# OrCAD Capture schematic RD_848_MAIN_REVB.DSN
size Custom; title: DER-804; rev: RevA
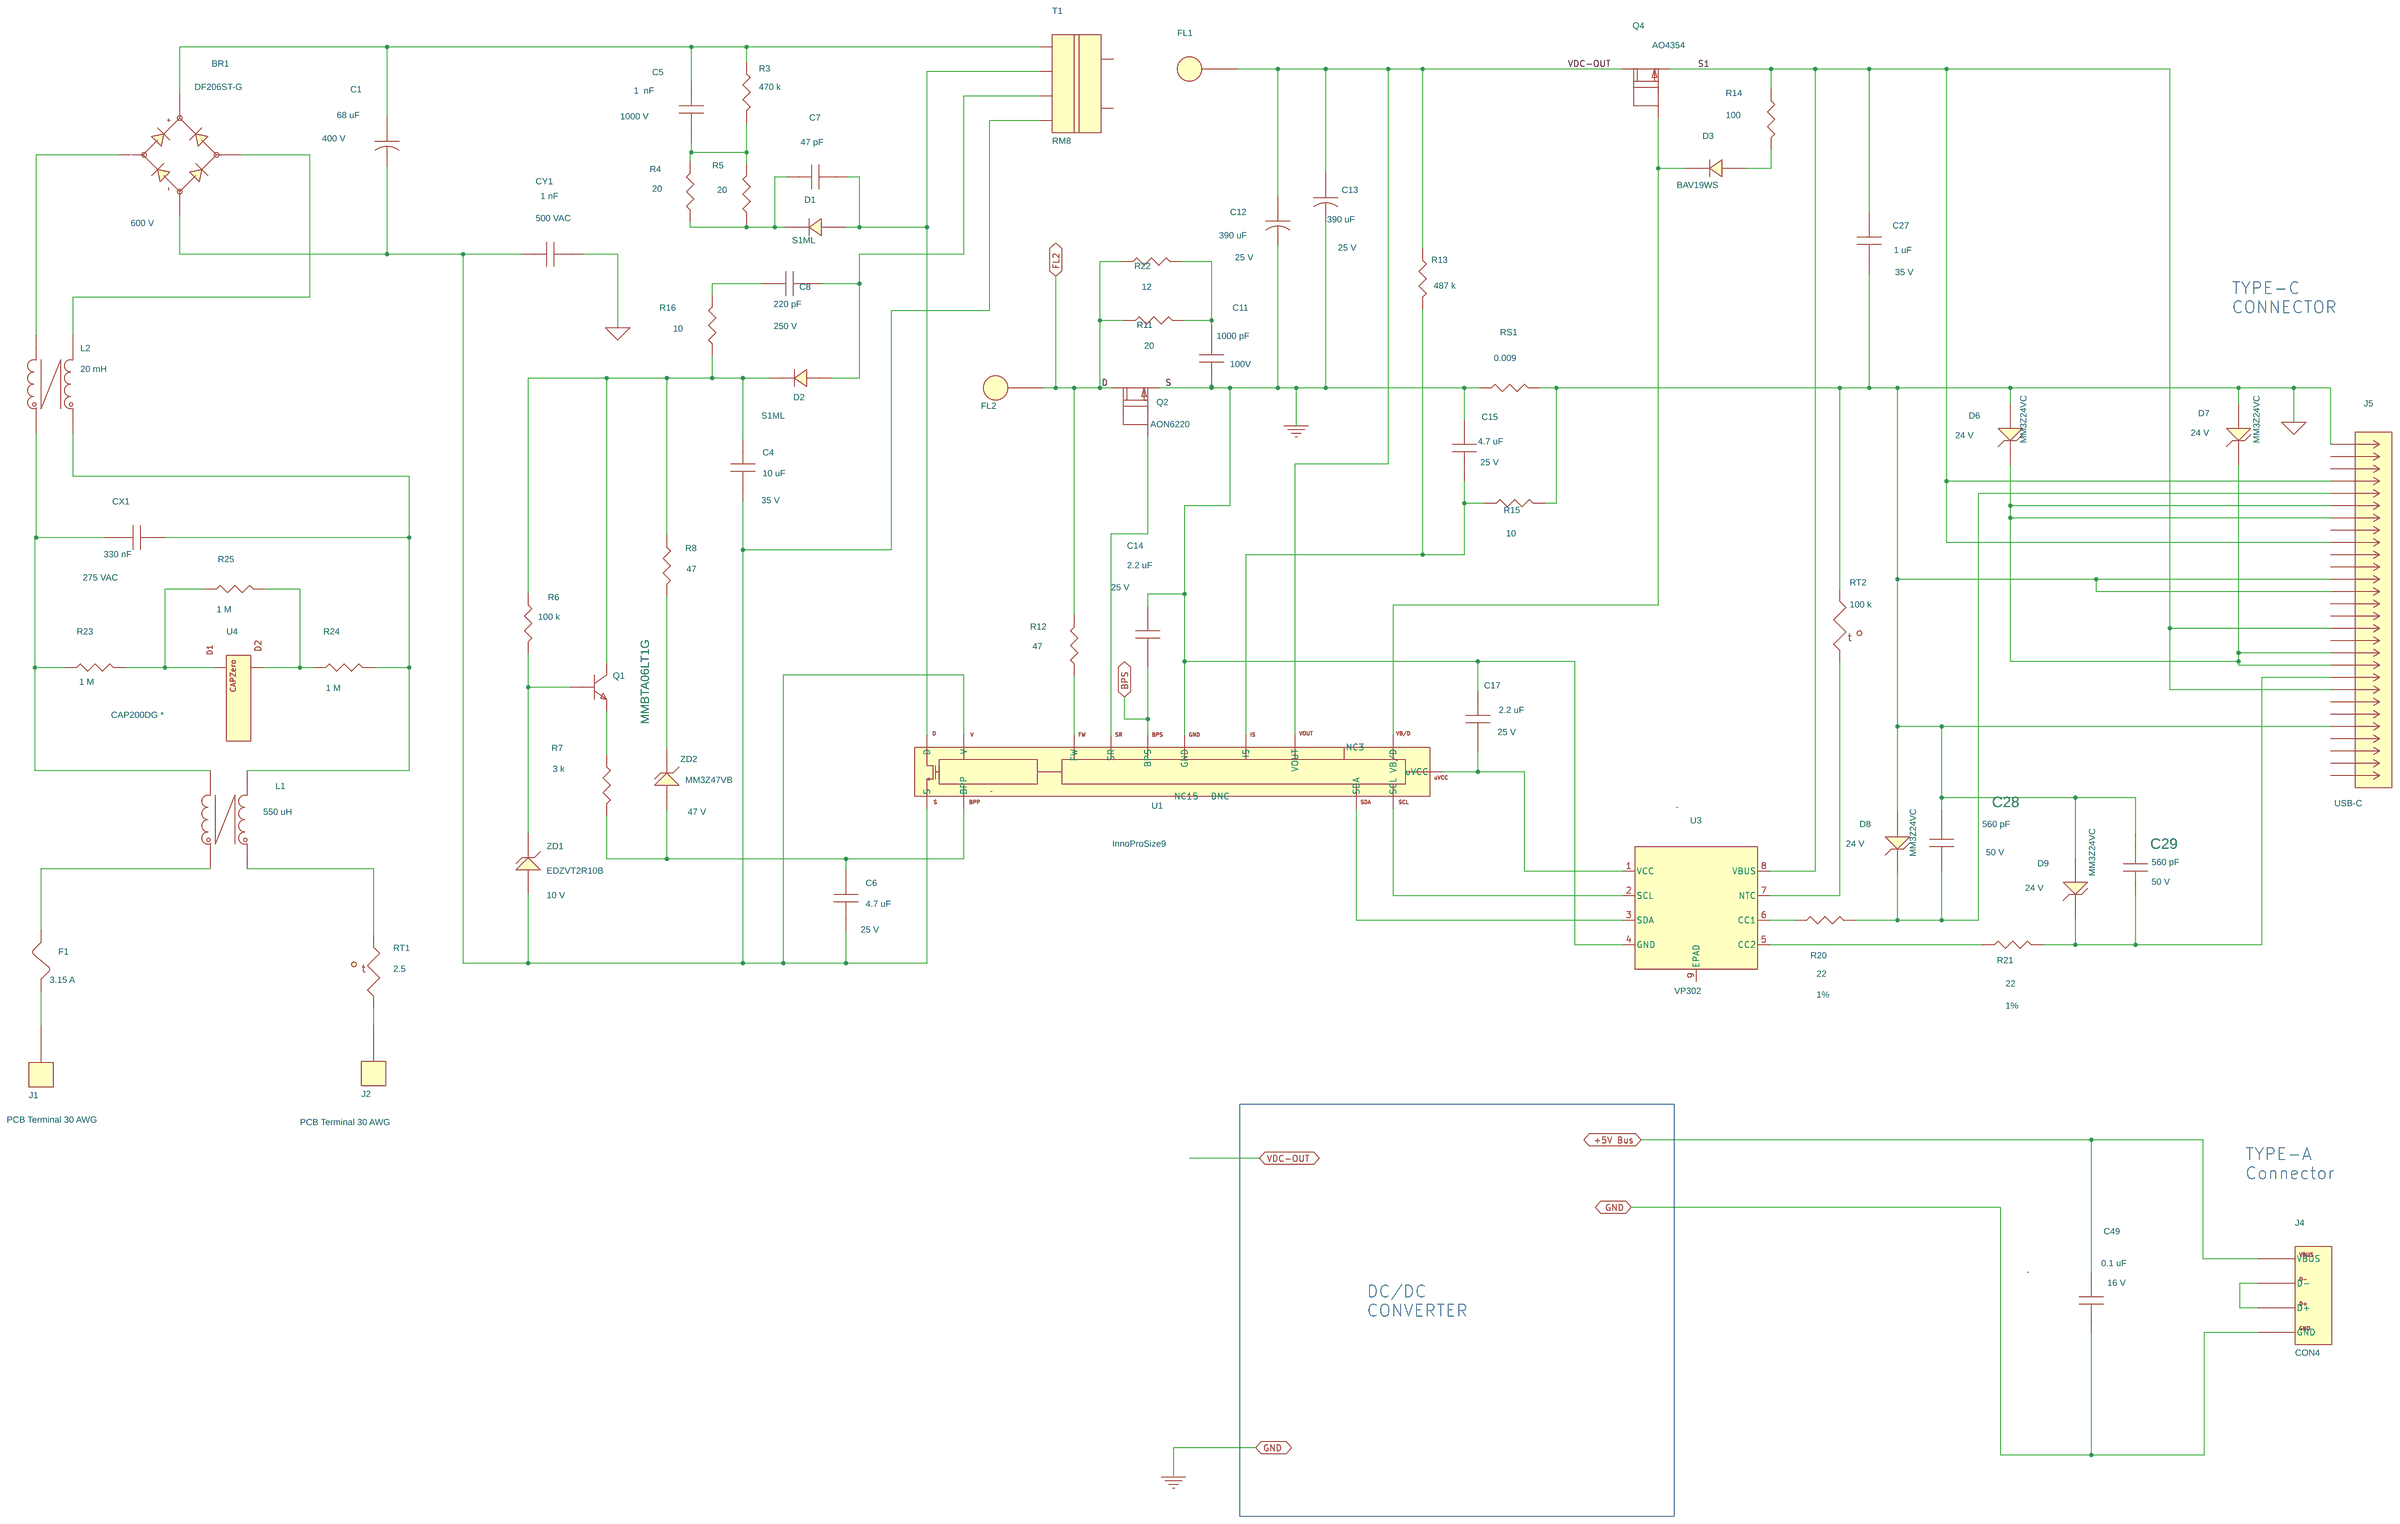
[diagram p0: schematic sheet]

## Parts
BR1  DF206ST-G  [pismddfs]
C1  68 uF  [pipolcapclyd630ls300040]
C4  10 uF  [pismc1206]
C5  1  nF  [pismc1206]
C6  4.7 uF  [pismc0805]
C7  47 pF  [pismc0805]
C8  220 pF  [pismc0603]
C11  1000 pF  [pismc0603]
C12  390 uF  [pipolcapcyld400ls200040]
C13  390 uF  [pipolcapcyld400ls200040]
C14  2.2 uF  [pismc0603]
C15  4.7 uF  [pismc0805]
C17  2.2 uF  [pismc0805]
C27  1 uF  [pismc0603]
C28  560 pF  [pismc0603]
C29  560 pF  [pismc0603]
C49  0.1 uF  [pismc0805]
CX1  330 nF  [pinp_xcaprad15x8p5x14Hd040]
CY1  1 nF  [pi_np475x200ls395d040]
D1  S1ML  [pi_sm_sod-123_12]
D2  S1ML  [pi_sm_sod-123_12]
D3  BAV19WS  [pismsod323]
D6  MM3Z24VC  [pismsod323F]
D7  MM3Z24VC  [pismsod323F]
D8  MM3Z24VC  [pismsod323F]
D9  MM3Z24VC  [pismsod323F]
F1  3.15 A  [pi_rst_microfuse]
FL1  Hole_70mils  [pi_hole_70mil]
FL2  Hole_70mils  [pi_hole_70mil]
J1  PCB Terminal 30 AWG  [pi_hole_30awg]
J2  PCB Terminal 30 AWG  [pi_hole_30awg]
J4  CON4  [pi_conn_usb4p_vert_Wurth]
J5  USB-C  [PI_DX07S024WJ3R400]
L1  550 uH  [pi_4p_ls5w4p5xd10p5mmd40]
L2  20 mH  [pi_toroid_CMC12p5x7p5_4pV]
Q1  MMBTA06LT1G  [pismsot23123_1]
Q2  AON6220  [pismpqfn5x6b]
Q4  AO4354  [pismso8]
R3  470 k  [pismr1206]
R4  20  [pismr1206]
R5  20  [pismr1206]
R6  100 k  [pismr0603]
R7  3 k  [pismr0603]
R8  47  [pismr0603]
R11  20  [pismr0805]
R12  47  [pismr0603]
R13  487 k  [pismr0603]
R14  100  [pismr0603]
R15  10  [pismr0603]
R16  10  [pismr0805]
R20  22  [pismr0402]
R21  22  [pismr0402]
R22  12  [pismr1206]
R23  1 M  [pismr1206]
R24  1 M  [pismr1206]
R25  1 M  [pismr1206]
RS1  0.009  [pismr0805]
RT1  2.5  [pi_rad150x300ls200d030]
RT2  100 k  [pismr0603]
T1  RM8  [pi_bobbin_rm8_6p_813]
U1  InnoProSize9  [pi_ic_insop_24d]
U3  VP302  [PI_SM_DFN-8]
U4  CAP200DG *  [pi_ic_smd_so8_capzero]
ZD1  EDZVT2R10B  [pi_sm_d_ssmini2p]
ZD2  MM3Z47VB  [pismsod323]

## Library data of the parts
BR1 = DIODE_BRIDGE_+-~~: Disp_Voltage: 600 V; Part Number: 15-00984-00
C1 = CAP_POL: ALT_SYMBOLS: pipolcapclyd630ls3000401000h; Disp_Voltage: 400 V; FPLIST: pipolcapclyd630ls300040,pipolcapclyd630ls3000401000h; Part Number: 20-01355-00; Voltage: 400 V
C4 = CAP_NP: ALT_SYMBOLS: pismc1206_1; Disp_Voltage: 35 V; FPLIST: pismc1206,pismc1206_1; Part Number: 20-09162-00; Voltage: 35 V
C5 = CAP_NP: Disp_Voltage: 1000 V; Part Number: 20-01131-00; Voltage: 1000 V
C6 C15 = CAP_NP: Disp_Voltage: 25 V; Part Number: 20-09022-00; Voltage: 25 V
C7 = CAP_NP: Disp_Voltage: 1000 V; Part Number: 20-01040-00; Voltage: 1000 V
C8 = CAP_NP: Disp_Voltage: 250 V; Part Number: 20-00840-00; Voltage: 250 V
C11 = CAP_NP: Disp_Voltage: 100V; Part Number: 20-09218-00; Voltage: 100V
C12 C13 = CAP_POL: ALT_SYMBOLS: pipolcapclyd395x630ls200030h; Disp_Voltage: 25 V; FPLIST: pipolcapcyld400ls200040,pipolcapclyd395x630ls200030h; Part Number: 20-08897-00; Voltage: 25 V
C14 = CAP_NP: ALT_SYMBOLS: pismc0603_1; Disp_Voltage: 25 V; FPLIST: pismc0603,pismc0603_1; Part Number: 20-09023-00; Voltage: 25 V
C17 = CAP_NP: Disp_Voltage: 25 V; Part Number: 20-08603-00; Voltage: 25 V
C27 = CAP_NP: ALT_SYMBOLS: pismc0603_1; Disp_Voltage: 35 V; FPLIST: pismc0603,pismc0603_1; Part Number: 20-09161-00; Voltage: 35 V
C28 C29 = CAP_NP: Disp_Voltage: 50 V; Part Number: 20-08982-00; Voltage: 50 V
C49 = CAP_NP: Disp_Voltage: 16 V; Part Number: 20-09164-00; Voltage: 16 V
CX1 = CAP_NP: ALT_SYMBOLS: pinp_xcaprad15x8p5x14Hd040H; Disp_Voltage: 275 VAC; FPLIST: pinp_xcaprad15x8p5x14Hd040,pinp_xcaprad15x8p5x14Hd040H; Part Number: 20-09095-00; Voltage: 275 VAC
CY1 = CAP_NP: COMPGROUP: 3; Disp_Voltage: 500 VAC; PCB Editor PCBFP: pinpycaprad540x290ls400040; Part Number: 20-01061-00; Voltage: 500 VAC
D1 = DIODE: COMPGROUP: 2; Part Number: 15-01027-00
D2 = DIODE: COMPGROUP: 1; Part Number: 15-01027-00
D3 = DIODE: Part Number: 15-00658-00
D6-D9 = DIODE_ZENER: Disp_Voltage: 24 V; Part Number: 15-01590-00
F1 = FUSE: ALT_SYMBOLS: pirstmicrofusehoz; COMPGROUP: 1; FPLIST: pi_rst_microfuse,pirstmicrofusehoz; Part Number: 40-00020-00
FL1 FL2 = FlyingLead: Part Number: 35-00282-00
J1 J2 = TERM_1Pin: Part Number: 35-00026-00
J4 = CON4_USB_1: Part Number: 35-00493-00
J5 = DX07S024WJ3R400: Part Number: 35-00495-00
L1 = TORRID_4P_12_0: Part Number: 32-00390-00
L2 = TORRID_4P_12_43a: Part Number: 32-00389-00
Q1 = NPN_BEC: Part Number: 55-00072-00
Q2 = FET_N_SGD_123_4_5678: Part Number: 50-00276-00
Q4 = FET_N_SGD_123_4_5678: Part Number: 50-00260-00
R3 = R: Part Number: 05-01416-00
R4 R5 = R: Part Number: 05-01311-00
R6 = R: Disp_Tol: 1%; Part Number: 05-01174-00
R7 = R: Part Number: 05-01699-00
R8 = R: ALT_SYMBOLS: pismr0603_1; FPLIST: pismr0603,pismr0603_1; Part Number: 05-01656-00
R11 = R: Part Number: 05-01478-00
R12 = R: ALT_SYMBOLS: pismr0603_1; Part Number: 05-01656-00
R13 = R: Disp_Tol: 1%; Part Number: 05-01240-00
R14 = R: Part Number: 05-01664-00
R15 = R: Disp_Tol: 1%; Part Number: 05-00886-00
R16 = R: Part Number: 05-01471-00
R20 R21 = R: COMPGROUP: 1; Disp_Tol: 1%; Part Number: 05-05631-00
R22 = R: Part Number: 05-01306-00
R23-R25 = R: Part Number: 05-01424-00
RS1 = R: Disp_Tol: 1%; Part Number: 05-06508-00
RT1 = THERMISTOR: ALT_SYMBOLS: pirad400x300ls200040_h; FPLIST: pi_rad150x300ls200d030,pirad400x300ls200040_h; Part Number: 90-00040-00
RT2 = THERMISTOR: Part Number: 90-00063-00
T1 = BRM8_6P_4-2: Part Number: 25-01163-00
U1 = DEV_InnoPro: Part Number: 10-01092-00
U3 = VP302: Part Number: 45-00495-00
U4 = CAPZero: Part Number: 10-00958-00
ZD1 = DIODE_ZENER: Disp_Voltage: 10 V; Part Number: 15-01591-00
ZD2 = DIODE_ZENER: Disp_Voltage: 47 V; Part Number: 15-01340-00

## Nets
+5V Bus: C49.1 J4.1(VBUS)
GND: C11.1 C12.2 C13.2 C14.1 C15.1 C17.1 C49.2 J4.4(GND) Q2.1(S) RS1.1 U1.2(GND) U3.4(GND)
GND_SIGNAL: C27.2 C28.2 C29.2 CY1.2 D6.2 D7.2 D8.2 D9.2 J5.A1 J5.A12 J5.B1 J5.B12 R15.2 RS1.2 RT2.1
BPS: C14.2 U1.4(BPS)
FL2: FL2.1 Q2.5(D) R11.2 R12.1 R22.2
NC3: U1.3(NC3)
S1: C27.1 J5.A4 J5.A9 J5.B4 J5.B9 Q4.1(S) R14.1 U3.8(VBUS)
VDC-OUT: C12.1 C13.1 FL1.1 Q4.5(D) R13.1 U1.10(VOUT)
N12696113: BR1.1 C1.1 C5.1 R3.1 T1.1
N12696321: C7.2 D1.2 T1.2 U1.24(D)
N12696371: C5.2 R3.2 R4.2 R5.2
N12696403: BR1.2 C1.2 C4.2 C6.2 CY1.1 T1.4 U1.13(V) U1.16(S) ZD1.2
N12696521: BR1.3 L2.3
N12696529: BR1.4 L2.2
N12696569: C7.1 D1.1 R4.1 R5.1
N12696753: C8.1 R16.2
N12696761: C8.2 D2.2 T1.3
N12696785: C11.2 R11.1 R22.1
N12696901: C4.1 D2.1 Q1.3(COLLECTOR) R6.1 R8.1 R16.1
N12697221: C15.2 R13.2 R15.1 U1.1(IS)
N12697259: Q2.4(G) U1.9(SR)
N12697307: R12.2 U1.11(FW)
N12697427: Q1.1(BASE) R6.2 ZD1.1
N12697475: R8.2 ZD2.1
N12697497: J2.1 RT1.1
N12697517: Q1.2(EMITTER) R7.1
N12697613: C6.1 R7.2 U1.14(BPP) ZD2.2
N12856532: L1.1 RT1.2
N12860506: CX1.1 L1.2 L2.1 R24.2
N12860535: CX1.2 L1.3 L2.4 R23.1
N12939410: C17.2 U1.7(uVCC) U3.1(VCC)
N12939527: D3.1 Q4.4(G) U1.8(VB/D)
N12962608: D3.2 R14.2
N12962926: D6.1 D7.1 J5.A6 J5.A7 J5.B6 J5.B7
N12962950: C28.1 D8.1 J5.A5 R20.1
N12963022: RT2.2 U3.7(NTC)
N12963250: C29.1 D9.1 J5.B5 R21.1
N12963278: R20.2 U3.6(CC1)
N12963330: R21.2 U3.5(CC2)
N12967856: U1.5(SCL) U3.2(SCL)
N12967863: U1.6(SDA) U3.3(SDA)
N12982735: F1.2 L1.4
N12983558: F1.1 J1.1
N12984078: R23.2 R25.1 U4.2(D1)
N12984082: R24.1 R25.2 U4.7(D2)
N13015620: J4.2(D-) J4.3(D+)

Not connected (* = marked no-connect by the designer): J5 27 28 29 30 A2 A3 A8 A10 A11 B2 B3 B8 B10 B11; Q2 2(S2) 3(S3) 6(D6) 7(D7) 8(D8); Q4 2(S2) 3(S3) 6(D6) 7(D7) 8(D8); T1 5 6; U1 12(DNC) 15(NC15); U3 9(EPAD); U4 1(NC1) 3(NC2) 4(NC3) 5(NC4) 6(NC5) 8(NC8)

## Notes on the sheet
- TYPE-C
  CONNECTOR
- TYPE-A
  Connector
- DC/DC
  CONVERTER
